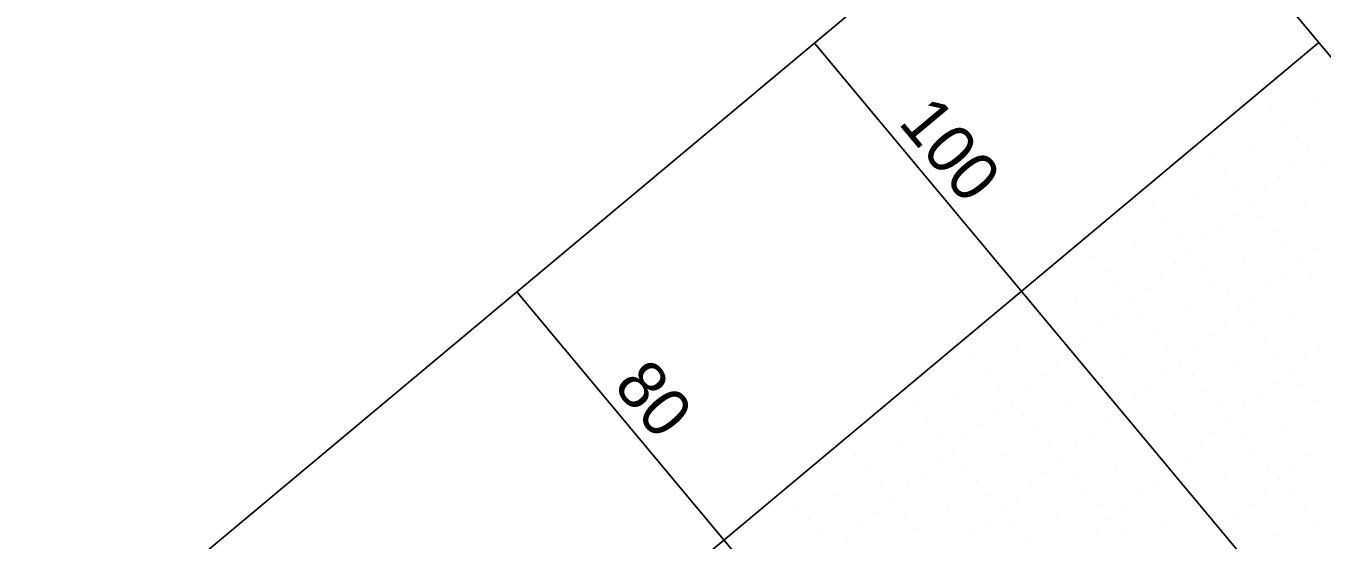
# Model space of a CAD drawing. Extents: x 2042995 to 2043795, y 305365 to 306249.
# Drawn here: x 2043127.8 to 2043194.7, y 306038.2 to 306064.7 of the extents above; entities that cross this region are included whole.
import ezdxf

# ---------------------------------------------------------------- set-up
doc = ezdxf.new("R2010")
doc.units = 0
for name, color, linetype in [('BR_BORDER LINES', 7, 'Continuous'), ('BR_GRID DOTS', 7, 'Continuous'), ('BR_GRID LINES', 7, 'Continuous'), ('BR_TEXT', 7, 'Continuous')]:
    doc.layers.add(name, color=color, linetype=linetype)

msp = doc.modelspace()

# ---------------------------------------------------------------- linework, layer by layer
at = {"layer": 'BR_BORDER LINES'}
for p, q in [((2043026.498, 305945.211), (2043348.857, 306214.443)), ((2043183.839, 306076.621), (2043615.462, 305559.826)), ((2043194.523, 306063.829), (2043041.019, 305935.624))]:
    msp.add_line(p, q, dxfattribs=at)
at = {"layer": 'BR_GRID DOTS'}
for p, q in [((2043194.27, 306061.012), (2043194.27, 306061.012)), ((2043192.094, 306060.498), (2043192.094, 306060.498)), ((2043192.735, 306059.73), (2043192.735, 306059.73)), ((2043193.376, 306058.963), (2043193.376, 306058.963)), ((2043191.2, 306058.448), (2043191.2, 306058.448)), ((2043194.017, 306058.195), (2043194.017, 306058.195)), ((2043189.024, 306057.934), (2043189.024, 306057.934)), ((2043193.249, 306057.554), (2043193.249, 306057.554)), ((2043194.658, 306057.428), (2043194.658, 306057.428)), ((2043189.665, 306057.166), (2043189.665, 306057.166)), ((2043192.482, 306056.913), (2043192.482, 306056.913)), ((2043190.306, 306056.399), (2043190.306, 306056.399)), ((2043191.714, 306056.272), (2043191.714, 306056.272)), ((2043188.13, 306055.884), (2043188.13, 306055.884)), ((2043190.947, 306055.631), (2043190.947, 306055.631)), ((2043185.954, 306055.37), (2043185.954, 306055.37)), ((2043190.179, 306054.99), (2043190.179, 306054.99)), ((2043191.588, 306054.864), (2043191.588, 306054.864)), ((2043193.764, 306055.378), (2043193.764, 306055.378)), ((2043186.595, 306054.602), (2043186.595, 306054.602)), ((2043189.412, 306054.349), (2043189.412, 306054.349)), ((2043192.229, 306054.096), (2043192.229, 306054.096)), ((2043187.236, 306053.834), (2043187.236, 306053.834)), ((2043188.644, 306053.708), (2043188.644, 306053.708)), ((2043182.884, 306052.805), (2043182.884, 306052.805)), ((2043185.06, 306053.32), (2043185.06, 306053.32)), ((2043187.877, 306053.067), (2043187.877, 306053.067)), ((2043190.694, 306052.814), (2043190.694, 306052.814)), ((2043192.87, 306053.328), (2043192.87, 306053.328)), ((2043194.278, 306053.202), (2043194.278, 306053.202)), ((2043187.109, 306052.426), (2043187.109, 306052.426)), ((2043188.518, 306052.299), (2043188.518, 306052.299)), ((2043193.511, 306052.561), (2043193.511, 306052.561)), ((2043183.525, 306052.038), (2043183.525, 306052.038)), ((2043186.342, 306051.785), (2043186.342, 306051.785)), ((2043189.159, 306051.532), (2043189.159, 306051.532)), ((2043192.743, 306051.92), (2043192.743, 306051.92)), ((2043194.152, 306051.793), (2043194.152, 306051.793)), ((2043181.99, 306050.756), (2043181.99, 306050.756)), ((2043184.166, 306051.27), (2043184.166, 306051.27)), ((2043185.574, 306051.144), (2043185.574, 306051.144)), ((2043189.8, 306050.764), (2043189.8, 306050.764)), ((2043191.976, 306051.279), (2043191.976, 306051.279)), ((2043184.807, 306050.503), (2043184.807, 306050.503)), ((2043187.624, 306050.25), (2043187.624, 306050.25)), ((2043191.208, 306050.638), (2043191.208, 306050.638)), ((2043184.039, 306049.862), (2043184.039, 306049.862)), ((2043185.448, 306049.735), (2043185.448, 306049.735)), ((2043190.441, 306049.997), (2043190.441, 306049.997)), ((2043193.258, 306049.744), (2043193.258, 306049.744)), ((2043183.272, 306049.221), (2043183.272, 306049.221)), ((2043186.089, 306048.968), (2043186.089, 306048.968)), ((2043189.673, 306049.356), (2043189.673, 306049.356)), ((2043191.082, 306049.229), (2043191.082, 306049.229)), ((2043178.92, 306048.192), (2043178.92, 306048.192)), ((2043182.504, 306048.58), (2043182.504, 306048.58)), ((2043186.73, 306048.2), (2043186.73, 306048.2)), ((2043188.138, 306048.074), (2043188.138, 306048.074)), ((2043188.906, 306048.715), (2043188.906, 306048.715)), ((2043191.723, 306048.462), (2043191.723, 306048.462)), ((2043194.54, 306048.209), (2043194.54, 306048.209)), ((2043176.743, 306047.677), (2043176.743, 306047.677)), ((2043181.737, 306047.939), (2043181.737, 306047.939)), ((2043184.554, 306047.686), (2043184.554, 306047.686)), ((2043187.371, 306047.433), (2043187.371, 306047.433)), ((2043192.364, 306047.694), (2043192.364, 306047.694)), ((2043193.773, 306047.568), (2043193.773, 306047.568)), ((2043177.385, 306046.91), (2043177.385, 306046.91)), ((2043180.969, 306047.298), (2043180.969, 306047.298)), ((2043186.603, 306046.792), (2043186.603, 306046.792)), ((2043190.188, 306047.18), (2043190.188, 306047.18)), ((2043193.005, 306046.927), (2043193.005, 306046.927)), ((2043178.026, 306046.142), (2043178.026, 306046.142)), ((2043180.202, 306046.657), (2043180.202, 306046.657)), ((2043185.836, 306046.151), (2043185.836, 306046.151)), ((2043188.012, 306046.665), (2043188.012, 306046.665)), ((2043192.237, 306046.286), (2043192.237, 306046.286)), ((2043193.646, 306046.159), (2043193.646, 306046.159)), ((2043175.849, 306045.628), (2043175.849, 306045.628)), ((2043179.434, 306046.016), (2043179.434, 306046.016)), ((2043185.068, 306045.51), (2043185.068, 306045.51)), ((2043188.653, 306045.898), (2043188.653, 306045.898)), ((2043191.47, 306045.645), (2043191.47, 306045.645)), ((2043194.287, 306045.392), (2043194.287, 306045.392)), ((2043173.673, 306045.113), (2043173.673, 306045.113)), ((2043177.899, 306044.734), (2043177.899, 306044.734)), ((2043178.667, 306045.375), (2043178.667, 306045.375)), ((2043181.484, 306045.122), (2043181.484, 306045.122)), ((2043184.301, 306044.869), (2043184.301, 306044.869)), ((2043189.294, 306045.13), (2043189.294, 306045.13)), ((2043190.702, 306045.004), (2043190.702, 306045.004)), ((2043174.314, 306044.346), (2043174.314, 306044.346)), ((2043177.132, 306044.093), (2043177.132, 306044.093)), ((2043179.308, 306044.607), (2043179.308, 306044.607)), ((2043183.533, 306044.228), (2043183.533, 306044.228)), ((2043187.118, 306044.616), (2043187.118, 306044.616)), ((2043189.935, 306044.363), (2043189.935, 306044.363)), ((2043192.752, 306044.11), (2043192.752, 306044.11)), ((2043174.955, 306043.578), (2043174.955, 306043.578)), ((2043176.364, 306043.452), (2043176.364, 306043.452)), ((2043179.949, 306043.84), (2043179.949, 306043.84)), ((2043182.766, 306043.587), (2043182.766, 306043.587)), ((2043189.167, 306043.722), (2043189.167, 306043.722)), ((2043190.576, 306043.595), (2043190.576, 306043.595)), ((2043172.779, 306043.064), (2043172.779, 306043.064)), ((2043175.596, 306042.811), (2043175.596, 306042.811)), ((2043180.59, 306043.072), (2043180.59, 306043.072)), ((2043181.998, 306042.946), (2043181.998, 306042.946)), ((2043188.4, 306043.081), (2043188.4, 306043.081)), ((2043191.217, 306042.828), (2043191.217, 306042.828)), ((2043170.603, 306042.549), (2043170.603, 306042.549)), ((2043174.829, 306042.17), (2043174.829, 306042.17)), ((2043176.238, 306042.043), (2043176.238, 306042.043)), ((2043178.414, 306042.558), (2043178.414, 306042.558)), ((2043181.231, 306042.305), (2043181.231, 306042.305)), ((2043184.048, 306042.052), (2043184.048, 306042.052)), ((2043187.632, 306042.44), (2043187.632, 306042.44)), ((2043191.858, 306042.06), (2043191.858, 306042.06)), ((2043194.034, 306042.575), (2043194.034, 306042.575)), ((2043171.244, 306041.781), (2043171.244, 306041.781)), ((2043174.061, 306041.528), (2043174.061, 306041.528)), ((2043180.463, 306041.664), (2043180.463, 306041.664)), ((2043181.872, 306041.537), (2043181.872, 306041.537)), ((2043186.865, 306041.799), (2043186.865, 306041.799)), ((2043189.682, 306041.546), (2043189.682, 306041.546)), ((2043193.267, 306041.934), (2043193.267, 306041.934)), ((2043171.885, 306041.014), (2043171.885, 306041.014)), ((2043173.294, 306040.887), (2043173.294, 306040.887)), ((2043176.879, 306041.275), (2043176.879, 306041.275)), ((2043179.696, 306041.023), (2043179.696, 306041.023)), ((2043182.513, 306040.77), (2043182.513, 306040.77)), ((2043186.097, 306041.158), (2043186.097, 306041.158)), ((2043192.499, 306041.293), (2043192.499, 306041.293)), ((2043169.709, 306040.499), (2043169.709, 306040.499)), ((2043172.526, 306040.246), (2043172.526, 306040.246)), ((2043177.52, 306040.508), (2043177.52, 306040.508)), ((2043178.928, 306040.381), (2043178.928, 306040.381)), ((2043185.33, 306040.517), (2043185.33, 306040.517)), ((2043191.731, 306040.652), (2043191.731, 306040.652)), ((2043193.14, 306040.525), (2043193.14, 306040.525)), ((2043167.533, 306039.985), (2043167.533, 306039.985)), ((2043171.759, 306039.605), (2043171.759, 306039.605)), ((2043173.167, 306039.479), (2043173.167, 306039.479)), ((2043175.343, 306039.993), (2043175.343, 306039.993)), ((2043178.161, 306039.74), (2043178.161, 306039.74)), ((2043180.978, 306039.487), (2043180.978, 306039.487)), ((2043183.154, 306040.002), (2043183.154, 306040.002)), ((2043184.562, 306039.876), (2043184.562, 306039.876)), ((2043190.196, 306039.37), (2043190.196, 306039.37)), ((2043190.964, 306040.011), (2043190.964, 306040.011)), ((2043193.781, 306039.758), (2043193.781, 306039.758)), ((2043168.174, 306039.217), (2043168.174, 306039.217)), ((2043170.991, 306038.964), (2043170.991, 306038.964)), ((2043173.808, 306038.711), (2043173.808, 306038.711)), ((2043177.393, 306039.099), (2043177.393, 306039.099)), ((2043178.802, 306038.973), (2043178.802, 306038.973)), ((2043183.795, 306039.234), (2043183.795, 306039.234)), ((2043186.612, 306038.981), (2043186.612, 306038.981)), ((2043189.429, 306038.729), (2043189.429, 306038.729)), ((2043194.422, 306038.99), (2043194.422, 306038.99)), ((2043168.815, 306038.45), (2043168.815, 306038.45)), ((2043170.224, 306038.323), (2043170.224, 306038.323)), ((2043176.626, 306038.458), (2043176.626, 306038.458)), ((2043179.443, 306038.205), (2043179.443, 306038.205)), ((2043183.027, 306038.593), (2043183.027, 306038.593)), ((2043184.436, 306038.467), (2043184.436, 306038.467)), ((2043192.246, 306038.476), (2043192.246, 306038.476))]:
    msp.add_line(p, q, dxfattribs=at)
at = {"layer": 'BR_GRID LINES'}
for p, q in [((2043168.489, 306063.801), (2043600.112, 305547.005)), ((2043153.138, 306050.98), (2043584.762, 305534.185))]:
    msp.add_line(p, q, dxfattribs=at)

# ---------------------------------------------------------------- texts
at = {"layer": 'BR_TEXT'}
for s, p in [('100', (2043172.774, 306059.684)), ('80', (2043158.06, 306046.102))]:
    msp.add_text(s, height=2.5, rotation=309.86836, dxfattribs=at).set_placement(p)

doc.saveas('drawing.dxf')
